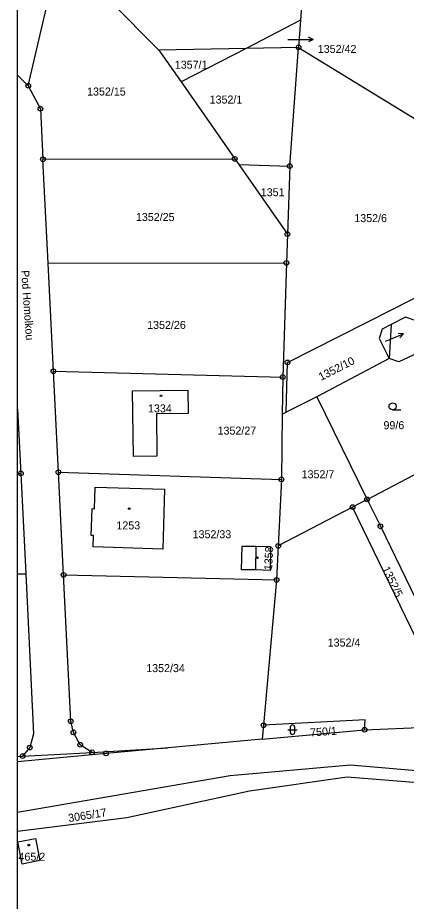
# Model space of a CAD drawing. Extents: x -728802 to -728097, y -1073200 to -1072700.
# Drawn here: x -728800 to -728717.3, y -1073061 to -1072873.2 of the extents above; entities that cross this region are included whole.
import ezdxf

# ---------------------------------------------------------------- set-up
doc = ezdxf.new("R2010")
doc.units = 0
for name, color, linetype in [('Hranice parcel', 7, 'Continuous'), ('K_31_listy_JŽM', 7, 'Continuous'), ('Pop  PČ popisy', 7, 'Continuous')]:
    doc.layers.add(name, color=color, linetype=linetype)

msp = doc.modelspace()

# ---------------------------------------------------------------- linework, layer by layer
at = {"layer": 'Hranice parcel'}
for p, q in [((-728738.63, -1072857.02), (-728739.84, -1072873.79)), ((-728797.74, -1072887.7), (-728791.98, -1072862.85)), ((-728739.84, -1072873.79), (-728751.41, -1072879.77)), ((-728739.84, -1072873.79), (-728740.25, -1072879.56)), ((-728751.41, -1072879.77), (-728769.94, -1072880.13)), ((-728751.41, -1072879.77), (-728765.2, -1072886.91)), ((-728740.25, -1072879.56), (-728751.41, -1072879.77)), ((-728742.13, -1072904.79), (-728740.25, -1072879.56)), ((-728740.25, -1072879.56), (-728715.25, -1072894.87)), ((-728769.94, -1072880.13), (-728765.2, -1072886.91)), ((-728765.2, -1072886.91), (-728753.8, -1072903.24)), ((-728794.64, -1072903.34), (-728753.8, -1072903.24)), ((-728793.51, -1072925.43), (-728794.64, -1072903.34)), ((-728753.8, -1072903.24), (-728752.95, -1072904.46)), ((-728752.95, -1072904.46), (-728742.63, -1072919.21)), ((-728752.95, -1072904.46), (-728742.13, -1072904.79)), ((-728742.13, -1072904.79), (-728742.63, -1072919.21)), ((-728742.63, -1072919.21), (-728742.84, -1072925.33)), ((-728793.51, -1072925.43), (-728742.84, -1072925.33)), ((-728792.39, -1072948.36), (-728793.51, -1072925.43)), ((-728742.84, -1072925.33), (-728743.59, -1072949.58)), ((-728720.53, -1072938.46), (-728720.94, -1072945.68)), ((-728723.09, -1072941.43), (-728720.94, -1072945.68)), ((-728720.94, -1072945.68), (-728736.37, -1072953.76)), ((-728718.94, -1072946.39), (-728720.94, -1072945.68)), ((-728791.32, -1072969.81), (-728792.39, -1072948.36)), ((-728792.39, -1072948.36), (-728743.59, -1072949.58)), ((-728743.59, -1072949.58), (-728743.7, -1072957.47)), ((-728736.37, -1072953.76), (-728742.89, -1072957.06)), ((-728736.37, -1072953.76), (-728725.65, -1072975.57)), ((-728800, -1072956.4), (-728799.32, -1072970.07)), ((-728743.7, -1072957.47), (-728742.89, -1072957.06)), ((-728720.25, -1072956.56), (-728718.5, -1072956.56)), ((-728743.7, -1072957.47), (-728743.88, -1072971.32)), ((-728725.65, -1072975.57), (-728702.01, -1072963.21)), ((-728800, -1072970.05), (-728799.32, -1072970.07)), ((-728799.32, -1072970.07), (-728798.26, -1072991.42)), ((-728790.23, -1072991.61), (-728791.32, -1072969.81)), ((-728791.32, -1072969.81), (-728743.88, -1072971.32)), ((-728743.88, -1072971.32), (-728744.57, -1072985.47)), ((-728725.65, -1072975.57), (-728728.75, -1072977.2)), ((-728728.75, -1072977.2), (-728744.57, -1072985.47)), ((-728707.72, -1073020.69), (-728728.75, -1072977.2)), ((-728749.34, -1072985.51), (-728749.41, -1072990.56)), ((-728744.57, -1072985.47), (-728744.92, -1072992.69)), ((-728800, -1072991.38), (-728798.26, -1072991.42)), ((-728790.23, -1072991.61), (-728744.92, -1072992.69)), ((-728744.92, -1072992.69), (-728747.69, -1073023.55)), ((-728747.69, -1073023.55), (-728747.95, -1073026.49)), ((-728747.95, -1073026.49), (-728726.2, -1073024.5)), ((-728742.55, -1073024.5), (-728740.55, -1073024.5)), ((-728742.05, -1073024), (-728742.05, -1073025)), ((-728741.05, -1073025), (-728741.05, -1073024)), ((-728726.2, -1073024.5), (-728709.27, -1073023.84)), ((-728747.95, -1073026.49), (-728768, -1073028.33)), ((-728784.16, -1073029.31), (-728768, -1073028.33)), ((-728800, -1073030.22), (-728798.94, -1073030.12)), ((-728798.94, -1073030.12), (-728784.16, -1073029.31))]:
    msp.add_line(p, q, dxfattribs=at)
for points in [[(-728791.98, -1072862.85), (-728780.33, -1072869.76), (-728769.94, -1072880.13)], [(-728800, -1072885.48), (-728797.74, -1072887.7)], [(-728797.74, -1072887.7), (-728795.17, -1072892.58), (-728794.64, -1072903.34)], [(-728742.89, -1072957.06), (-728742.61, -1072946.49), (-728720.35, -1072935.22), (-728712.92, -1072931.46), (-728710.98, -1072935.3)], [(-728710.98, -1072935.3), (-728715.44, -1072937.56), (-728717.46, -1072936.9), (-728720.53, -1072938.46)], [(-728720.53, -1072938.46), (-728722.43, -1072939.42), (-728723.09, -1072941.43)], [(-728713.2, -1072941.99), (-728713.91, -1072943.99), (-728718.94, -1072946.39)], [(-728775.39, -1072966.5), (-728775.55, -1072952.49), (-728763.79, -1072952.36), (-728763.74, -1072957.32), (-728770.49, -1072957.42), (-728770.39, -1072966.43), (-728775.39, -1072966.5)], [(-728783.51, -1072972.96), (-728768.74, -1072973.44), (-728769.13, -1072986.16), (-728783.92, -1072985.69), (-728783.85, -1072983.23), (-728784.36, -1072983.22), (-728784.17, -1072977.54), (-728783.65, -1072977.56), (-728783.51, -1072972.96)], [(-728725.65, -1072975.57), (-728722.83, -1072981.3), (-728715.29, -1072996.74)], [(-728749.41, -1072990.56), (-728752.36, -1072990.54), (-728752.25, -1072985.5), (-728749.34, -1072985.51), (-728746.2, -1072985.61), (-728746.31, -1072990.71), (-728749.41, -1072990.56)], [(-728798.26, -1072991.42), (-728796.65, -1073025.41), (-728797.41, -1073028.31), (-728798.94, -1073030.12)], [(-728784.16, -1073029.31), (-728786.68, -1073027.7), (-728788.13, -1073025.07), (-728788.7, -1073022.71), (-728790.23, -1072991.61)], [(-728726.2, -1073024.5), (-728726.04, -1073022.42), (-728747.69, -1073023.55)], [(-728768, -1073028.33), (-728781.17, -1073029.53), (-728800, -1073031.36)], [(-728800, -1073042), (-728754.78, -1073034.24), (-728729.22, -1073031.95), (-728711.87, -1073033.42), (-728687.08, -1073034.79), (-728677.64, -1073033.29)], [(-728800, -1073046.03), (-728776.74, -1073043.15), (-728750.7, -1073037.52), (-728729.9, -1073034.48), (-728716.63, -1073035.6), (-728685.42, -1073036.71), (-728685.04, -1073036.71)], [(-728799.99, -1073048.35), (-728796.17, -1073047.58), (-728795.28, -1073052.3), (-728799.02, -1073053.08), (-728799.99, -1073048.35)]]:
    msp.add_lwpolyline(points, dxfattribs=at)
for centre, radius in [((-728740.25, -1072879.56), 0.5), ((-728740.25, -1072879.56), 0.0303), ((-728797.74, -1072887.7), 0.5), ((-728797.74, -1072887.7), 0.0303), ((-728795.17, -1072892.58), 0.5), ((-728795.17, -1072892.58), 0.0303), ((-728794.64, -1072903.34), 0.5), ((-728794.64, -1072903.34), 0.0303), ((-728753.8, -1072903.24), 0.5), ((-728753.8, -1072903.24), 0.0303), ((-728742.13, -1072904.79), 0.5), ((-728742.13, -1072904.79), 0.0303), ((-728742.63, -1072919.21), 0.5), ((-728742.63, -1072919.21), 0.0303), ((-728742.84, -1072925.33), 0.5), ((-728742.84, -1072925.33), 0.0303), ((-728742.61, -1072946.49), 0.5), ((-728742.61, -1072946.49), 0.0303), ((-728792.39, -1072948.36), 0.5), ((-728792.39, -1072948.36), 0.0303), ((-728743.59, -1072949.58), 0.5), ((-728743.59, -1072949.58), 0.0303), ((-728769.49, -1072953.58), 0.175), ((-728720.25, -1072955.81), 0.75), ((-728799.32, -1072970.07), 0.5), ((-728799.32, -1072970.07), 0.0303), ((-728791.32, -1072969.81), 0.5), ((-728791.32, -1072969.81), 0.0303), ((-728743.88, -1072971.32), 0.5), ((-728743.88, -1072971.32), 0.0303), ((-728725.65, -1072975.57), 0.5), ((-728725.65, -1072975.57), 0.0303), ((-728776.26, -1072977.56), 0.175), ((-728728.75, -1072977.2), 0.5), ((-728728.75, -1072977.2), 0.0303), ((-728722.83, -1072981.3), 0.5), ((-728722.83, -1072981.3), 0.0303), ((-728744.57, -1072985.47), 0.5), ((-728744.57, -1072985.47), 0.0303), ((-728749.02, -1072987.98), 0.175), ((-728790.23, -1072991.61), 0.5), ((-728790.23, -1072991.61), 0.0303), ((-728744.92, -1072992.69), 0.5), ((-728744.92, -1072992.69), 0.0303), ((-728788.7, -1073022.71), 0.5), ((-728788.7, -1073022.71), 0.0303), ((-728788.13, -1073025.07), 0.5), ((-728747.69, -1073023.55), 0.5), ((-728747.69, -1073023.55), 0.0303), ((-728726.2, -1073024.5), 0.5), ((-728726.2, -1073024.5), 0.0303), ((-728788.13, -1073025.07), 0.0303), ((-728797.41, -1073028.31), 0.5), ((-728797.41, -1073028.31), 0.0303), ((-728786.68, -1073027.7), 0.5), ((-728786.68, -1073027.7), 0.0303), ((-728798.94, -1073030.12), 0.5), ((-728798.94, -1073030.12), 0.0303), ((-728784.16, -1073029.31), 0.5), ((-728784.16, -1073029.31), 0.0303), ((-728781.17, -1073029.53), 0.5), ((-728781.17, -1073029.53), 0.0303), ((-728797.63, -1073049.02), 0.175)]:
    msp.add_circle(centre, radius, dxfattribs=at)
for centre, start, end in [((-728741.55, -1073024), 0, 180), ((-728741.55, -1073025), 180, 359.9879)]:
    msp.add_arc(centre, 0.5, start, end, dxfattribs=at)
at = {"layer": 'K_31_listy_JŽM'}
msp.add_lwpolyline([(-728800, -1073200), (-728800, -1072700), (-728100, -1072700), (-728100, -1073200), (-728800, -1073200)], dxfattribs=at)
at = {"layer": 'Pop  PČ popisy'}
for p, q in [((-728742.51, -1072877.88), (-728740.15, -1072877.89)), ((-728740.15, -1072877.89), (-728737.15, -1072877.89)), ((-728737.15, -1072877.89), (-728738.15, -1072877.39)), ((-728737.15, -1072877.89), (-728738.15, -1072878.39)), ((-728721.74, -1072941.99), (-728720.71, -1072941.56)), ((-728720.71, -1072941.56), (-728717.95, -1072940.39)), ((-728717.95, -1072940.39), (-728719.07, -1072940.32)), ((-728717.95, -1072940.39), (-728718.67, -1072941.24))]:
    msp.add_line(p, q, dxfattribs=at)

# ---------------------------------------------------------------- texts
at = {"layer": 'Hranice parcel'}
for s, p in [('1352/42', (-728736.15, -1072880.74)), ('1357/1', (-728766.57, -1072884.09)), ('1352/15', (-728785.23, -1072889.79)), ('1352/1', (-728759.16, -1072891.49)), ('1351', (-728748.28, -1072911.18)), ('1352/25', (-728774.84, -1072916.44)), ('1352/6', (-728728.39, -1072916.68)), ('1352/26', (-728772.45, -1072939.37)), ('1334', (-728772.27, -1072957.1)), ('99/6', (-728722.18, -1072960.66)), ('1352/27', (-728757.47, -1072961.82)), ('1352/7', (-728739.59, -1072971.09)), ('1253', (-728778.99, -1072981.95)), ('1352/33', (-728762.78, -1072983.83)), ('1352/4', (-728734.04, -1073006.83)), ('1352/34', (-728772.65, -1073012.27)), ('465/2', (-728799.82, -1073052.33))]:
    msp.add_text(s, height=1.7, dxfattribs=at).set_placement(p)
for s, rotation, p in [('Pod Homolkou', 274, (-728799.26, -1072926.96)), ('1352/10', 27, (-728735.45, -1072950.42)), ('1358', 87, (-728745.89, -1072990.67)), ('1352/5', 296, (-728722.54, -1072990.29)), ('750/1', 4, (-728737.72, -1073025.95)), ('3065/17', 9, (-728789.1, -1073044.14))]:
    msp.add_text(s, height=1.7, rotation=rotation, dxfattribs=at).set_placement(p)

doc.saveas('drawing.dxf')
